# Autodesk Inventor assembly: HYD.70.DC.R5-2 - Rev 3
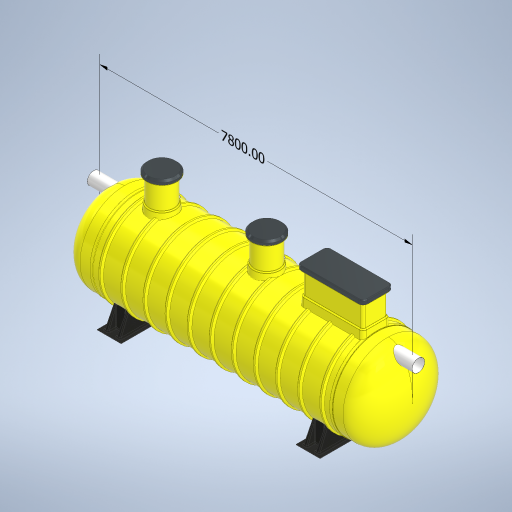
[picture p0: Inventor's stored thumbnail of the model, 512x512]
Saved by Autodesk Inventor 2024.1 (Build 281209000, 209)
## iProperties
Created: 2023-08
Part Number: HYD.70.DC.R5-2 - Rev 3
Document SubType Name: Assembly
Designer: macga
Author: macga
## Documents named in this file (43)
- D:\$ Protector Vault\Workspace\Automation Files\1. Protector Stardard Products\HydroProtectors\FAMILY\HYD.70 - Vernon\HYD.70.DC.R5-2 - Rev 3.iam
- D:\$ Protector Vault\Workspace\1. Protector Stardard Products\HydroProtectors\FAMILY\HORIZONTAL TANK - IPART\HORIZONTAL TANK - IPART.ipt
- D:\$ Protector Vault\Workspace\1. Protector Stardard Products\HydroProtectors\FAMILY\DOME - IPART\DOME - IPART.ipt
- D:\$ Protector Vault\Workspace\1. Protector Stardard Products\HydroProtectors\FAMILY\FOOT - IPART\FRP Foot - IPART.ipt
- D:\$ Protector Vault\Workspace\1. Protector Stardard Products\HydroProtectors\FAMILY\ACDTUBE - IPART\ACDTUBE - IPART.ipt
- D:\$ Protector Vault\Workspace\1. Protector Stardard Products\HydroProtectors\FAMILY\ACD FLOAT VALVE - IPART\ACD.FloatValve - IASSY.iam
- D:\$ Protector Vault\Workspace\1. Protector Stardard Products\HydroProtectors\FAMILY\COALESCER FILTER - IPART\CF-R5.iam
- D:\$ Protector Vault\Workspace\1. Protector Stardard Products\HydroProtectors\FAMILY\SU.600Dia Manway Adaptor - IPART\SU.MWA.HS.6R - IPART.ipt
- D:\$ Protector Vault\Workspace\1. Protector Stardard Products\HydroProtectors\FAMILY\WIN.600mmDiaManwayRiser - IPART\600mmDia Manway Riser.ipt
- D:\$ Protector Vault\Workspace\1. Protector Stardard Products\HydroProtectors\Automation Files\600mmDia Manway Cover.ipt
- D:\$ Protector Vault\Workspace\1. Protector Stardard Products\HydroProtectors\FAMILY\OUTLET ELBOW - IPART\OUTLET ELBOW - IPART.ipt
- D:\$ Protector Vault\Workspace\1. Protector Stardard Products\HydroProtectors\Coalescer Guide Rail.ipt
- D:\$ Protector Vault\Workspace\1. Protector Stardard Products\HydroProtectors\ISO 4065 Pipe DN315x2.5xS63 - 1365.ipt
- D:\$ Protector Vault\Workspace\1. Protector Stardard Products\HydroProtectors\FAMILY\INLET PIPE ELBOW- IPART\INLET PIPE ELBOW- IPART\InletPipeElbow.300D.ipt
- D:\$ Protector Vault\Workspace\1. Protector Stardard Products\HydroProtectors\FAMILY\INLET PIPE ELBOW- IPART\INLET PIPE ELBOW- IPART.ipt
- D:\$ Protector Vault\Workspace\1. Protector Stardard Products\HydroProtectors\Upper Guide Rai Braket.ipt
- D:\$ Protector Vault\Workspace\1. Protector Stardard Products\Standard Components\Flanged Vent.ipt
- D:\$ Protector Vault\Workspace\1. Protector Stardard Products\HydroProtectors\HYD Oil Probe\Oil Probe Assembly.iam
- D:\$ Protector Vault\Workspace\1. Protector Stardard Products\HydroProtectors\FAMILY\HORIZONTAL TANK - IPART\HORIZONTAL TANK - IPART\WIN.HB.2200x6040L-10.ipt
- D:\$ Protector Vault\Workspace\1. Protector Stardard Products\HydroProtectors\FAMILY\DOME - IPART\DOME - IPART\SU.DOME.2200-10.ipt
- D:\$ Protector Vault\Workspace\1. Protector Stardard Products\HydroProtectors\FAMILY\FOOT - IPART\FRP Foot - IPART\SU.HS.FOOT.2200.ipt
- D:\$ Protector Vault\Workspace\1. Protector Stardard Products\HydroProtectors\FAMILY\HYD.BAFFLE - IPART\SU.BAFFLE.2200\SU.BAFFLE.2200.ipt
- D:\$ Protector Vault\Workspace\1. Protector Stardard Products\HydroProtectors\FAMILY\HYD.BAFFLE - IPART\SU.BAFFLE.2200.ipt
- D:\$ Protector Vault\Workspace\1. Protector Stardard Products\HydroProtectors\FAMILY\SU.600Dia Manway Adaptor - IPART\Horizontal 600mmDia Manway Adaptor (FLANGED) SU.MWA.HS.6R-1850-1850\SU.MWA.HS.6R-2200.ipt
- D:\$ Protector Vault\Workspace\1. Protector Stardard Products\HydroProtectors\FAMILY\ACD Base - IPART\SU.ACDBASE.2200\SU.ACDBASE.2200-450ACDFV.ipt
- D:\$ Protector Vault\Workspace\1. Protector Stardard Products\HydroProtectors\FAMILY\ACD Base - IPART\SU.ACDBASE.2200.ipt
- D:\$ Protector Vault\Workspace\1. Protector Stardard Products\HydroProtectors\HYD.70 300 Outlet Vertical.ipt
- D:\$ Protector Vault\Workspace\1. Protector Stardard Products\HydroProtectors\FAMILY\ACDTUBE - IPART\ACDTUBE - IPART\ACDTUBE.450-1846.ipt
- D:\$ Protector Vault\Workspace\1. Protector Stardard Products\HydroProtectors\FAMILY\ACD FLOAT VALVE - IPART\ACD.FloatValve - IASSY\ACD.FVALVE.450.ASSY.iam
- D:\$ Protector Vault\Workspace\1. Protector Stardard Products\HydroProtectors\FAMILY\OUTLET ELBOW - IPART\OUTLET ELBOW - IPART\OutletPipeElbow.300D-100DCoupling.ipt
- D:\$ Protector Vault\Workspace\1. Protector Stardard Products\Xtremeprotector\Vault\Chain.ipt
- D:\$ Protector Vault\Workspace\1. Protector Stardard Products\Xtremeprotector\Vault\Lifting Eye.ipt
- D:\$ Protector Vault\Workspace\1. Protector Stardard Products\HydroProtectors\FAMILY\WIN.600mmDiaManwayRiser - IPART\600mmDia Manway Riser\SU.600mmDia.ManwayRiser.600-10.ipt
- D:\$ Protector Vault\Workspace\1. Protector Stardard Products\HydroProtectors\FAMILY\Coalescer Guide Rail-018.ipt
- D:\$ Protector Vault\Workspace\1. Protector Stardard Products\HydroProtectors\FAMILY\Coalescer Guide Rail-019.ipt
- D:\$ Protector Vault\Workspace\Automation Files\1. Protector Stardard Products\HydroProtectors\FAMILY\CF.BASE - IPART\CF BASE DUAL - IPART\SU.CFBASE.2200.DUAL\SU.CFBASE.2200.B1.2-R5-OP.300.ipt
- D:\$ Protector Vault\Workspace\Automation Files\1. Protector Stardard Products\HydroProtectors\FAMILY\CF.BASE - IPART\CF BASE DUAL - IPART\SU.CFBASE.2200.DUAL.ipt
- D:\$ Protector Vault\Workspace\1. Protector Stardard Products\HydroProtectors\FAMILY\SU.600X1500ManwayRiserAdaptor - IPART\600x1500mm Manway Adaptor - IPART\SU.MRADAPTOR.2200.600Lx1500W.ipt
- D:\$ Protector Vault\Workspace\1. Protector Stardard Products\HydroProtectors\FAMILY\SU.600X1500ManwayRiserAdaptor - IPART\600x1500mm Manway Adaptor - IPART.ipt
- D:\$ Protector Vault\Workspace\1. Protector Stardard Products\HydroProtectors\Automation Files\Access Risers\600x1500 Manway Riser.ipt
- D:\$ Protector Vault\Workspace\1. Protector Stardard Products\Standard Components\600x1500 Manway Cover ST\600x1500 Manway Cover Class D ST-02.ipt
- D:\$ Protector Vault\Workspace\1. Protector Stardard Products\Standard Components\600x1500 Manway Cover ST.ipt
- D:\$ Protector Vault\Workspace\1. Protector Stardard Products\Xtremeprotector\Vault\Chain\Chain-39.ipt
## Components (38 placed, 26 different names)
1. WIN.HB.2200x6040L-10:1
2. SU.DOME.2200-10:1 — Mate:1, Mate:3, Mate:78, Mate:83
3. ISO 4065 Pipe DN315x2.5xS63 - 1365:2 — Mate:83, Mate:84
4. InletPipeElbow.300D:1 — Mate:84
5. SU.DOME.2200-10:2 — Mate:2, Mate:4
6. SU.HS.FOOT.2200:1 — Mate:74, Mate:75
7. SU.HS.FOOT.2200:2 — Mate:76, Mate:77
8. SU.BAFFLE.2200:1 — Mate:78, Mate:79
9. SU.ACDBASE.2200-450ACDFV:1 — Mate:14, Mate:79, Mate:82
10. ACDTUBE.450-1846:1 — Mate:14, Mate:15, Mate:38, Mate:42
11. ACD.FVALVE.450.ASSY:1 [sub-assembly] — Mate:15, Mate:82
12. SU.CFBASE.2200.B1.2-R5-OP.300:1
13. CF-R5:1 [sub-assembly] — Mate:19, Mate:93, Tangent:3
14. CF-R5:2 [sub-assembly] — Mate:21, Mate:94, Tangent:5
15. HYD.70 300 Outlet Vertical:1
16. OutletPipeElbow.300D-100DCoupling:2 — Mate:53, Mate:54
17. ISO 4065 Pipe DN315x2.5xS63 - 1365:1 — Mate:53, Mate:54
18. SU.MWA.HS.6R-2200:2 — Mate:38, Mate:39, Mate:40, Mate:41, Mate:68, Mate:69, Tangent:2
19. SU.600mmDia.ManwayRiser.600-10:1 — Mate:30, Mate:31, Mate:40, Mate:41
20. 600mmDia Manway Cover:2 — Mate:30, Mate:31, Angle:2
21. Coalescer Guide Rail-018:1 — Mate:47, Mate:49, Mate:62, Mate:63, Flush:5, Flush:10
22. Coalescer Guide Rail-019:2 — Mate:50, Mate:64, Mate:65, Flush:6, Flush:10
23. Lifting Eye:2 — Tangent:6
24. Lifting Eye:1 — Tangent:4
25. Chain-39:2 — Mate:94, Tangent:5, Tangent:6
26. Chain-39:1 — Mate:93, Tangent:3, Tangent:4
27. 600x1500 Manway Riser:1 — Mate:61, Flush:3, Flush:4
28. 600x1500 Manway Cover Class D ST-02:1 — Mate:61, Flush:3, Flush:4
29. Upper Guide Rai Braket:1 — Mate:62, Mate:63, Flush:5
30. Upper Guide Rai Braket:2 — Mate:64, Mate:65, Flush:6
31. Flanged Vent:1 — Mate:66, Mate:67
32. Flanged Vent:2 — Mate:68, Mate:69
33. Flanged Vent:3
34. SU.MRADAPTOR.2200.600Lx1500W:1 — Angle:3
35. SU.MWA.HS.6R-2200:3 — Mate:42, Mate:43, Mate:44, Mate:45, Mate:66, Mate:67, Mate:73, Flush:8
36. SU.600mmDia.ManwayRiser.600-10:2 — Mate:32, Mate:33, Mate:44, Mate:45
37. 600mmDia Manway Cover:1 — Mate:32, Mate:33
38. Oil Probe Assembly:1 [sub-assembly] — Mate:73, Flush:8
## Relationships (59: Mate 46, Flush 6, Tangent 5, Angle 2)
- Mate:1: SU.DOME.2200-10:1
- Mate:2: SU.DOME.2200-10:2
- Mate:3: SU.DOME.2200-10:1
- Mate:4: SU.DOME.2200-10:2
- Mate:14: SU.ACDBASE.2200-450ACDFV:1 ↔ ACDTUBE.450-1846:1
- Mate:15: ACDTUBE.450-1846:1 ↔ ACD.FVALVE.450.ASSY:1
- Mate:19: CF-R5:1
- Mate:21: CF-R5:2
- Mate:30: SU.600mmDia.ManwayRiser.600-10:1 ↔ 600mmDia Manway Cover:2
- Mate:31: SU.600mmDia.ManwayRiser.600-10:1 ↔ 600mmDia Manway Cover:2
- Mate:32: SU.600mmDia.ManwayRiser.600-10:2 ↔ 600mmDia Manway Cover:1
- Mate:33: SU.600mmDia.ManwayRiser.600-10:2 ↔ 600mmDia Manway Cover:1
- Mate:38: ACDTUBE.450-1846:1 ↔ SU.MWA.HS.6R-2200:2
- Mate:39: SU.MWA.HS.6R-2200:2
- Mate:40: SU.MWA.HS.6R-2200:2 ↔ SU.600mmDia.ManwayRiser.600-10:1
- Mate:41: SU.MWA.HS.6R-2200:2 ↔ SU.600mmDia.ManwayRiser.600-10:1
- Mate:42: ACDTUBE.450-1846:1 ↔ SU.MWA.HS.6R-2200:3
- Mate:43: SU.MWA.HS.6R-2200:3
- Mate:44: SU.MWA.HS.6R-2200:3 ↔ SU.600mmDia.ManwayRiser.600-10:2
- Mate:45: SU.MWA.HS.6R-2200:3 ↔ SU.600mmDia.ManwayRiser.600-10:2
- Mate:47: Coalescer Guide Rail-018:1
- Mate:49: Coalescer Guide Rail-018:1
- Mate:50: Coalescer Guide Rail-019:2
- Mate:53: OutletPipeElbow.300D-100DCoupling:2 ↔ ISO 4065 Pipe DN315x2.5xS63 - 1365:1
- Mate:54: OutletPipeElbow.300D-100DCoupling:2 ↔ ISO 4065 Pipe DN315x2.5xS63 - 1365:1
- Mate:61: 600x1500 Manway Riser:1 ↔ 600x1500 Manway Cover Class D ST-02:1
- Flush:3: 600x1500 Manway Riser:1 ↔ 600x1500 Manway Cover Class D ST-02:1
- Flush:4: 600x1500 Manway Riser:1 ↔ 600x1500 Manway Cover Class D ST-02:1
- Mate:62: Coalescer Guide Rail-018:1 ↔ Upper Guide Rai Braket:1
- Mate:63: Coalescer Guide Rail-018:1 ↔ Upper Guide Rai Braket:1
- Flush:5: Coalescer Guide Rail-018:1 ↔ Upper Guide Rai Braket:1
- Mate:64: Coalescer Guide Rail-019:2 ↔ Upper Guide Rai Braket:2
- Mate:65: Coalescer Guide Rail-019:2 ↔ Upper Guide Rai Braket:2
- Flush:6: Coalescer Guide Rail-019:2 ↔ Upper Guide Rai Braket:2
- Mate:66: Flanged Vent:1 ↔ SU.MWA.HS.6R-2200:3
- Mate:67: Flanged Vent:1 ↔ SU.MWA.HS.6R-2200:3
- Mate:68: SU.MWA.HS.6R-2200:2 ↔ Flanged Vent:2
- Mate:69: SU.MWA.HS.6R-2200:2 ↔ Flanged Vent:2
- Angle:2: 600mmDia Manway Cover:2
- Tangent:2: SU.MWA.HS.6R-2200:2
- Mate:73: SU.MWA.HS.6R-2200:3 ↔ Oil Probe Assembly:1
- Flush:8: SU.MWA.HS.6R-2200:3 ↔ Oil Probe Assembly:1
- Mate:74: SU.HS.FOOT.2200:1
- Mate:75: SU.HS.FOOT.2200:1
- Mate:76: SU.HS.FOOT.2200:2
- Mate:77: SU.HS.FOOT.2200:2
- Mate:78: SU.DOME.2200-10:1 ↔ SU.BAFFLE.2200:1
- Mate:79: SU.BAFFLE.2200:1 ↔ SU.ACDBASE.2200-450ACDFV:1
- Mate:82: SU.ACDBASE.2200-450ACDFV:1 ↔ ACD.FVALVE.450.ASSY:1
- Mate:83: SU.DOME.2200-10:1 ↔ ISO 4065 Pipe DN315x2.5xS63 - 1365:2
- Mate:84: ISO 4065 Pipe DN315x2.5xS63 - 1365:2 ↔ InletPipeElbow.300D:1
- Flush:10: Coalescer Guide Rail-018:1 ↔ Coalescer Guide Rail-019:2
- Mate:93: CF-R5:1 ↔ Chain-39:1
- Tangent:3: CF-R5:1 ↔ Chain-39:1
- Tangent:4: Lifting Eye:1 ↔ Chain-39:1
- Mate:94: CF-R5:2 ↔ Chain-39:2
- Tangent:5: CF-R5:2 ↔ Chain-39:2
- Tangent:6: Lifting Eye:2 ↔ Chain-39:2
- Angle:3: SU.MRADAPTOR.2200.600Lx1500W:1
